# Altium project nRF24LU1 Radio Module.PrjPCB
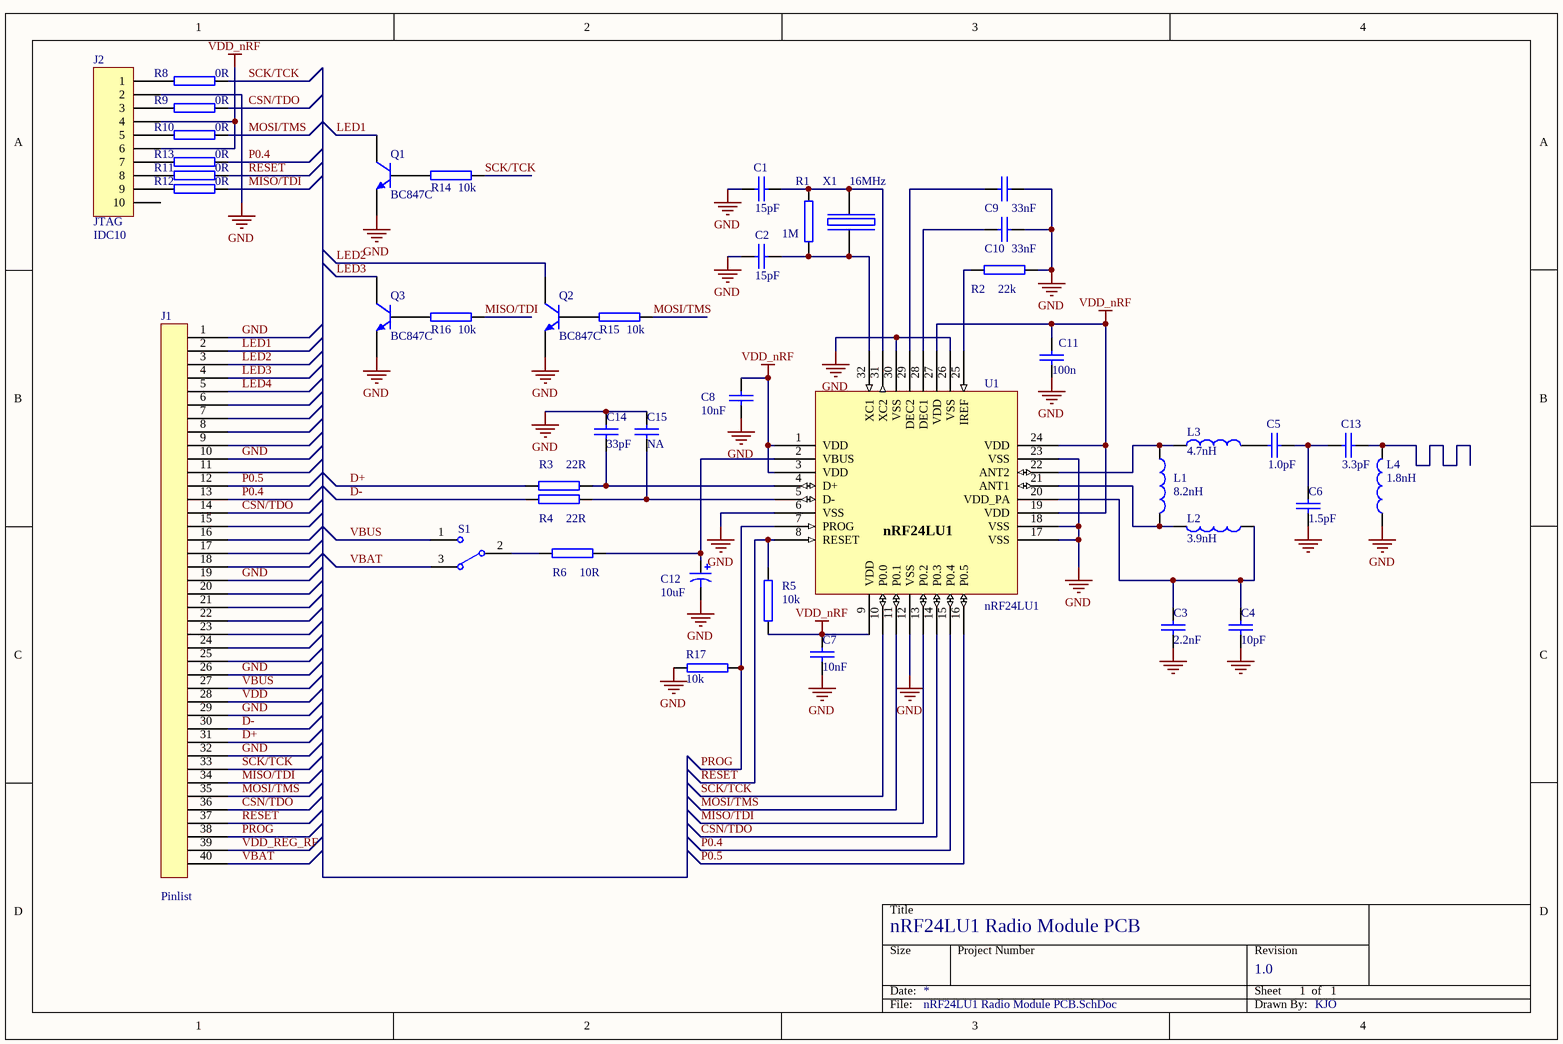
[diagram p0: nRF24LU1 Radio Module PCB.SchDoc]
title: nRF24LU1 ev.module
1 sheet, 43 parts. Net scope: global (net labels, ports and power ports of the same name join across sheets).
Board file: nRf24LU1 Radio Module PCB.PcbDoc

## Sheet nRF24LU1 Radio Module PCB.SchDoc: nRF24LU1 ev.module
size A4; Revision: 0.1; SheetNumber: 0; SheetTotal: 0; DrawnBy: KJO

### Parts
C1  value 15pF  [0402s]  (hidden comment: NPO, +/-2% 50V)
C2  value 15pF  [0402s]  (hidden comment: NPO, +/-2% 50V)
C3  value 2.2nF  [0402s]  (hidden comment: X7R, +/-10% 50V)
C4  value 10pF  [0402s]  (hidden comment: NP0 +/-0.25pF, 50V)
C5  value 1.0pF  [0402s]  (hidden comment: NP0 +/-0.1pF, 50V)
C6  value 1.5pF  [0402s]  (hidden comment: NP0 +/-0.1pF, 50V)
C7  value 10nF  [0402s]  (hidden comment: X7R, +/-10% 50V)
C8  value 10nF  [0402s]  (hidden comment: X7R, +/-10% 50V)
C9  value 33nF  [0402s]  (hidden comment: X7R, +/-10% 50V)
C10  value 33nF  [0402s]  (hidden comment: X7R, +/-10% 50V)
C11  value 100n  [0402s]  (hidden comment: X7R, +/-10% 50V)
C12  value 10uF  [C1206]  (hidden comment: Tantal  10V)
C13  value 3.3pF  [0402s]  (hidden comment: NP0 +/-0.25pF, 50V)
C14  value 33pF  [0402s]  (hidden comment: NP0, +/-10% 50V)
C15  value NA  [0402s]
J1  value Pinlist  [DIP40]  (hidden comment: Elfa 48-155-10)
J2  value IDC10  [IDC2x5]  (hidden comment: Header 2x5 pin)
L1  value 8.2nH  [0402s]  (hidden comment: Chip inductor +/-5%  Murata LQP15)
L2  value 3.9nH  [0402s]  (hidden comment: Chip Inductor +/-5%  Murata LQP15)
L3  value 4.7nH  [0402s]  (hidden comment: Chip inductor +/-5%  Murata LQP15)
L4  value 1.8nH  [0402s]  (hidden comment: Chip inductor +/-5% Murata LQP15)
Q1  BC847C  [SOT23]
Q2  BC847C  [SOT23]
Q3  BC847C  [SOT23]
R1  value 1M  [0402s]  (hidden comment: 5%)
R2  value 22k  [0402s]  (hidden comment: 1%)
R3  value 22R  [0402s]  (hidden comment: 5%)
R4  value 22R  [0402s]  (hidden comment: 5%)
R5  value 10k  [0402s]  (hidden comment: 5%)
R6  value 10R  [0402s]  (hidden comment: 5%)
R8  value 0R  [0402s]
R9  value 0R  [0402s]
R10  value 0R  [0402s]
R11  value 0R  [0402s]
R12  value 0R  [0402s]
R13  value 0R  [0402s]
R14  value 10k  [0402s]  (hidden comment: 5%)
R15  value 10k  [0402s]  (hidden comment: 5%)
R16  value 10k  [0402s]  (hidden comment: 5%)
R17  value 10k  [0402s]  (hidden comment: 5%)
S1  ELFA 35-365-21  [SW mini2]  (value not drawn)
U1  nRF24LU1  [QFN32L/5x5]
X1  value 16MHz  [BT-XTAL]  (hidden comment: TSX4025 16MHz, CL=9pF)

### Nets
GND: C1.2 C2.1 C3.1 C4.1 C6.2 C7.2 C8.2 C9.2 C10.2 C11.2 C12.2 C14.2 C15.2 J1.1 J1.10 J1.19 J1.26 J1.29 J1.32 J2.2 L4.1 Q1.3(E) Q2.3(E) Q3.3(E) R2.1 R17.1 U1.6(VSS) U1.12(VSS) U1.17(VSS) U1.18(VSS) U1.23(VSS) U1.26(VSS) U1.30(VSS) X1.2(GND) X1.4(GND)
VDD_nRF: C7.1 C8.1 C11.1 J2.4 J2.6 R5.2 U1.1(VDD) U1.3(VDD) U1.9(VDD) U1.19(VDD) U1.24(VDD) U1.27(VDD)
CSN/TDO: J1.14 J1.36 R9.1 U1.14(P0.3)
D+: J1.31 R3.2
D-: J1.30 R4.2
LED1: J1.2 Q1.1(C)
LED2: J1.3 Q2.1(C)
LED3: J1.4 Q3.1(C)
LED4: J1.5
MISO/TDI: J1.34 R12.1 R16.1 U1.13(P0.2)
MOSI/TMS: J1.35 R10.1 R15.1 U1.11(P0.1)
P0.4: J1.13 R13.1 U1.15(P0.4)
P0.5: J1.12 U1.16(P0.5)
PROG: J1.38 R17.2 U1.7(PROG)
RESET: J1.37 R5.1 R11.1 U1.8(RESET)
SCK/TCK: J1.33 R8.1 R14.1 U1.10(P0.0)
VBAT: J1.40 S1.3
VBUS: J1.27 S1.1
VDD: J1.28
VDD_REG_RF: J1.39
NetC1_1: C1.1 R1.1 U1.31(XC2) X1.1(inp)
NetC2_2: C2.2 R1.2 U1.32(XC1) X1.3(out)
NetC3_2: C3.2 C4.2 L2.1 U1.20(VDD_PA)
NetC5_1: C5.1 C6.1 C13.2
NetC5_2: C5.2 L3.2
NetC9_1: C9.1 U1.29(DEC2)
NetC10_1: C10.1 U1.28(DEC1)
NetC12_1: C12.1 R6.1 U1.2(VBUS)
NetC13_1: C13.1 L4.2
NetC14_1: C14.1 R3.1 U1.4(D+)
NetC15_1: C15.1 R4.1 U1.5(D-)
NetJ2_1: J2.1 R8.2
NetJ2_3: J2.3 R9.2
NetJ2_5: J2.5 R10.2
NetJ2_7: J2.7 R13.2
NetJ2_8: J2.8 R11.2
NetJ2_9: J2.9 R12.2
NetL1_1: L1.1 L3.1 U1.22(ANT2)
NetL1_2: L1.2 L2.2 U1.21(ANT1)
NetQ1_2: Q1.2(B) R14.2
NetQ2_2: Q2.2(B) R15.2
NetQ3_2: Q3.2(B) R16.2
NetR2_2: R2.2 U1.25(IREF)
NetR6_2: R6.2 S1.2

Not connected (* = marked no-connect by the designer): J1 6 7 8 9 11 15 16 17 18 20 21 22 23 24 25; J2 10

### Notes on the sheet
- (near J2) JTAG
- Title
- nRF24LU1 Radio Module PCB
- Size
- Date:
- Project Number
- Sheet      1  of   1
- Revision
- 1.0
- File:
- Drawn By:
- KJO

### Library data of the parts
C1-C11 C13-C15 = CAP: Part Field 1: 0402
C12 = Cap Pol3: Polarized Capacitor (Surface Mount)
J1 = 40PIN
J2 = Header 10: Header, 10-Pin
L1-L4 = INDUCTOR1: Part Field 1: 0402
Q1-Q3 = NPN: NPN Bipolar Transistor; pin to pad: 2>3 3>2
R1 = RES2: Part Field 1: 0603
R2 R4 = RES2: Part Field 1: 1608[0603]
R3 = RES2: Part Field 1: 0603s
R5 R6 R8-R17 = RES2: Part Field 1: 0402
S1 = SW-SPDT: SPDT Subminiature Toggle Switch, Right Angle Mounting, Vertical Actuation; Revision 1: Jul-2002: Re-released for DXP Platform.; Revision 2: 17-Dec-2003: Schematic revised, PCB Footprint replaced.; Value: EAO type 1K2 straight pins
U1 = nRF24LU1: 2.4GHz Transceiver with USB
X1 = BT-XTAL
